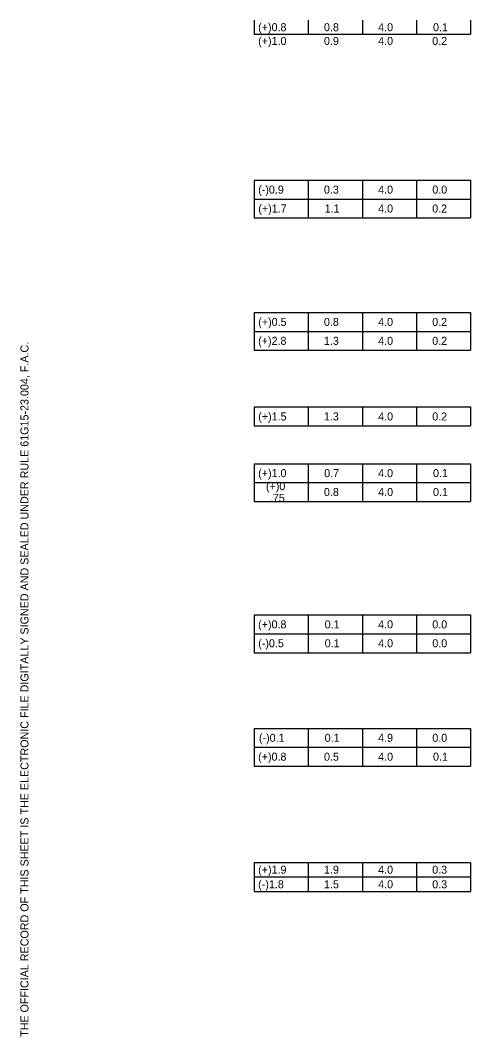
# Model space of a CAD drawing. Extents: x 0.03 to 1.66, y 0 to 0.87.
# Drawn here: x 1.332 to 1.659, y 0.004 to 0.743 of the extents above; entities that cross this region are included whole.
import ezdxf

# ---------------------------------------------------------------- set-up
doc = ezdxf.new("R2010")
doc.units = 0
for name, color, linetype in [('SumBoxBorder_dp', 7, 'Continuous'), ('SumBoxLines_dp', 7, 'Continuous'), ('SumBoxLinesMin_dp', 7, 'Continuous'), ('TextLabel', 7, 'Continuous'), ('TextMisc', 7, 'Continuous')]:
    doc.layers.add(name, color=color, linetype=linetype)

msp = doc.modelspace()

# ---------------------------------------------------------------- linework, layer by layer
at = {"layer": 'SumBoxBorder_dp'}
for p, q in [((1.6595, 0.74335), (1.6595, 0.73335)), ((1.6595, 0.62714), (1.6595, 0.59966)), ((1.6595, 0.53093), (1.6595, 0.50344)), ((1.6595, 0.46221), (1.6595, 0.44847)), ((1.6595, 0.42098), (1.6595, 0.39349)), ((1.6595, 0.31102), (1.6595, 0.28353)), ((1.6595, 0.22855), (1.6595, 0.20107)), ((1.6595, 0.13109), (1.6595, 0.10985))]:
    msp.add_line(p, q, dxfattribs=at)
at = {"layer": 'SumBoxLines_dp'}
for p, q in [((1.50206, 0.74335), (1.50206, 0.73335)), ((1.54142, 0.74335), (1.54142, 0.73335)), ((1.54142, 0.74335), (1.54142, 0.73335)), ((1.58078, 0.74335), (1.58078, 0.73335)), ((1.58078, 0.74335), (1.58078, 0.73335)), ((1.62014, 0.74335), (1.62014, 0.73335)), ((1.62014, 0.74335), (1.62014, 0.73335)), ((1.50206, 0.62714), (1.50206, 0.59966)), ((1.54142, 0.62714), (1.54142, 0.59966)), ((1.54142, 0.62714), (1.54142, 0.59966)), ((1.58078, 0.62714), (1.58078, 0.59966)), ((1.58078, 0.62714), (1.58078, 0.59966)), ((1.62014, 0.62714), (1.62014, 0.59966)), ((1.62014, 0.62714), (1.62014, 0.59966)), ((1.50206, 0.53093), (1.50206, 0.50344)), ((1.54142, 0.53093), (1.54142, 0.50344)), ((1.54142, 0.53093), (1.54142, 0.50344)), ((1.58078, 0.53093), (1.58078, 0.50344)), ((1.58078, 0.53093), (1.58078, 0.50344)), ((1.62014, 0.53093), (1.62014, 0.50344)), ((1.62014, 0.53093), (1.62014, 0.50344)), ((1.50206, 0.46221), (1.50206, 0.44847)), ((1.54142, 0.46221), (1.54142, 0.44847)), ((1.54142, 0.46221), (1.54142, 0.44847)), ((1.58078, 0.46221), (1.58078, 0.44847)), ((1.58078, 0.46221), (1.58078, 0.44847)), ((1.62014, 0.46221), (1.62014, 0.44847)), ((1.62014, 0.46221), (1.62014, 0.44847)), ((1.50206, 0.42098), (1.50206, 0.39349)), ((1.54142, 0.42098), (1.54142, 0.39349)), ((1.54142, 0.42098), (1.54142, 0.39349)), ((1.58078, 0.42098), (1.58078, 0.39349)), ((1.58078, 0.42098), (1.58078, 0.39349)), ((1.62014, 0.42098), (1.62014, 0.39349)), ((1.62014, 0.42098), (1.62014, 0.39349)), ((1.50206, 0.31102), (1.50206, 0.28353)), ((1.54142, 0.31102), (1.54142, 0.28353)), ((1.54142, 0.31102), (1.54142, 0.28353)), ((1.58078, 0.31102), (1.58078, 0.28353)), ((1.58078, 0.31102), (1.58078, 0.28353)), ((1.62014, 0.31102), (1.62014, 0.28353)), ((1.62014, 0.31102), (1.62014, 0.28353)), ((1.50206, 0.22855), (1.50206, 0.20107)), ((1.54142, 0.22855), (1.54142, 0.20107)), ((1.54142, 0.22855), (1.54142, 0.20107)), ((1.58078, 0.22855), (1.58078, 0.20107)), ((1.58078, 0.22855), (1.58078, 0.20107)), ((1.62014, 0.22855), (1.62014, 0.20107)), ((1.62014, 0.22855), (1.62014, 0.20107)), ((1.50206, 0.13109), (1.50206, 0.10985)), ((1.54142, 0.13109), (1.54142, 0.10985)), ((1.54142, 0.13109), (1.54142, 0.10985)), ((1.58078, 0.13109), (1.58078, 0.10985)), ((1.58078, 0.13109), (1.58078, 0.10985)), ((1.62014, 0.13109), (1.62014, 0.10985)), ((1.62014, 0.13109), (1.62014, 0.10985))]:
    msp.add_line(p, q, dxfattribs=at)
at = {"layer": 'SumBoxLinesMin_dp'}
for p, q in [((1.50206, 0.73335), (1.6595, 0.73335)), ((1.50206, 0.73335), (1.6595, 0.73335)), ((1.50206, 0.62714), (1.6595, 0.62714)), ((1.50206, 0.6134), (1.6595, 0.6134)), ((1.50206, 0.6134), (1.6595, 0.6134)), ((1.50206, 0.59966), (1.6595, 0.59966)), ((1.50206, 0.59966), (1.6595, 0.59966)), ((1.50206, 0.53093), (1.6595, 0.53093)), ((1.50206, 0.51719), (1.6595, 0.51719)), ((1.50206, 0.51719), (1.6595, 0.51719)), ((1.50206, 0.50344), (1.6595, 0.50344)), ((1.50206, 0.50344), (1.6595, 0.50344)), ((1.50206, 0.46221), (1.6595, 0.46221)), ((1.50206, 0.44847), (1.6595, 0.44847)), ((1.50206, 0.44847), (1.6595, 0.44847)), ((1.50206, 0.42098), (1.6595, 0.42098)), ((1.50206, 0.40723), (1.6595, 0.40723)), ((1.50206, 0.40723), (1.6595, 0.40723)), ((1.50206, 0.39349), (1.6595, 0.39349)), ((1.50206, 0.39349), (1.6595, 0.39349)), ((1.50206, 0.31102), (1.6595, 0.31102)), ((1.50206, 0.29728), (1.6595, 0.29728)), ((1.50206, 0.29728), (1.6595, 0.29728)), ((1.50206, 0.28353), (1.6595, 0.28353)), ((1.50206, 0.28353), (1.6595, 0.28353)), ((1.50206, 0.22855), (1.6595, 0.22855)), ((1.50206, 0.21481), (1.6595, 0.21481)), ((1.50206, 0.21481), (1.6595, 0.21481)), ((1.50206, 0.20107), (1.6595, 0.20107)), ((1.50206, 0.20107), (1.6595, 0.20107)), ((1.50206, 0.13109), (1.6595, 0.13109)), ((1.50206, 0.12047), (1.6595, 0.12047)), ((1.50206, 0.12047), (1.6595, 0.12047)), ((1.50206, 0.10985), (1.6595, 0.10985))]:
    msp.add_line(p, q, dxfattribs=at)

# ---------------------------------------------------------------- texts
at = {"layer": 'TextLabel'}
for s, p in [('(+)0.8', (1.50504, 0.73543)), ('0.8', (1.55286, 0.73543)), ('4.0', (1.59225, 0.73543)), ('0.1', (1.63212, 0.73543)), ('(+)1.0', (1.50506, 0.72544)), ('0.9', (1.55287, 0.72544)), ('4.0', (1.59225, 0.72544)), ('0.2', (1.63156, 0.72544)), ('(-)0.9', (1.50505, 0.61736)), ('0.3', (1.55284, 0.61736)), ('4.0', (1.59225, 0.61736)), ('0.0', (1.63161, 0.61736)), ('(+)1.7', (1.50518, 0.60361)), ('1.1', (1.5534, 0.60361)), ('4.0', (1.59225, 0.60361)), ('0.2', (1.63156, 0.60361)), ('(+)0.5', (1.50509, 0.52115)), ('0.8', (1.55286, 0.52115)), ('4.0', (1.59225, 0.52115)), ('0.2', (1.63156, 0.52115)), ('(+)2.8', (1.50504, 0.5074)), ('1.3', (1.55284, 0.5074)), ('4.0', (1.59225, 0.5074)), ('0.2', (1.63156, 0.5074)), ('(+)1.5', (1.50509, 0.45242)), ('1.3', (1.55284, 0.45242)), ('4.0', (1.59225, 0.45242)), ('0.2', (1.63156, 0.45242)), ('(+)1.0', (1.50506, 0.41119)), ('0.7', (1.55301, 0.41119)), ('4.0', (1.59225, 0.41119)), ('0.1', (1.63212, 0.41119)), ('(+)0', (1.51071, 0.40169)), ('0.8', (1.55286, 0.39745)), ('4.0', (1.59225, 0.39745)), ('0.1', (1.63212, 0.39745)), ('.75', (1.51355, 0.3932)), ('(+)0.8', (1.50504, 0.30123)), ('0.1', (1.5534, 0.30123)), ('4.0', (1.59225, 0.30123)), ('0.0', (1.63161, 0.30123)), ('(-)0.5', (1.50509, 0.28749)), ('0.1', (1.5534, 0.28749)), ('4.0', (1.59225, 0.28749)), ('0.0', (1.63161, 0.28749)), ('(-)0.1', (1.50558, 0.21877)), ('0.1', (1.5534, 0.21877)), ('4.9', (1.59223, 0.21877)), ('0.0', (1.63161, 0.21877)), ('(+)0.8', (1.50504, 0.20502)), ('0.5', (1.55291, 0.20502)), ('4.0', (1.59225, 0.20502)), ('0.1', (1.63212, 0.20502)), ('(+)1.9', (1.50505, 0.12287)), ('1.9', (1.55287, 0.12287)), ('4.0', (1.59225, 0.12287)), ('0.3', (1.63156, 0.12287)), ('(-)1.8', (1.50504, 0.11225)), ('1.5', (1.55291, 0.11225)), ('4.0', (1.59225, 0.11225)), ('0.3', (1.63156, 0.11225))]:
    msp.add_text(s, height=0.005831, dxfattribs=at).set_placement(p)
at = {"layer": 'TextMisc'}
msp.add_text('THE OFFICIAL RECORD OF THIS SHEET IS THE ELECTRONIC FILE DIGITALLY SIGNED AND SEALED UNDER RULE 61G15-23.004, F.A.C.', height=0.00583333, rotation=90, dxfattribs=at).set_placement((1.33811, 0.00419))

doc.saveas('drawing.dxf')
